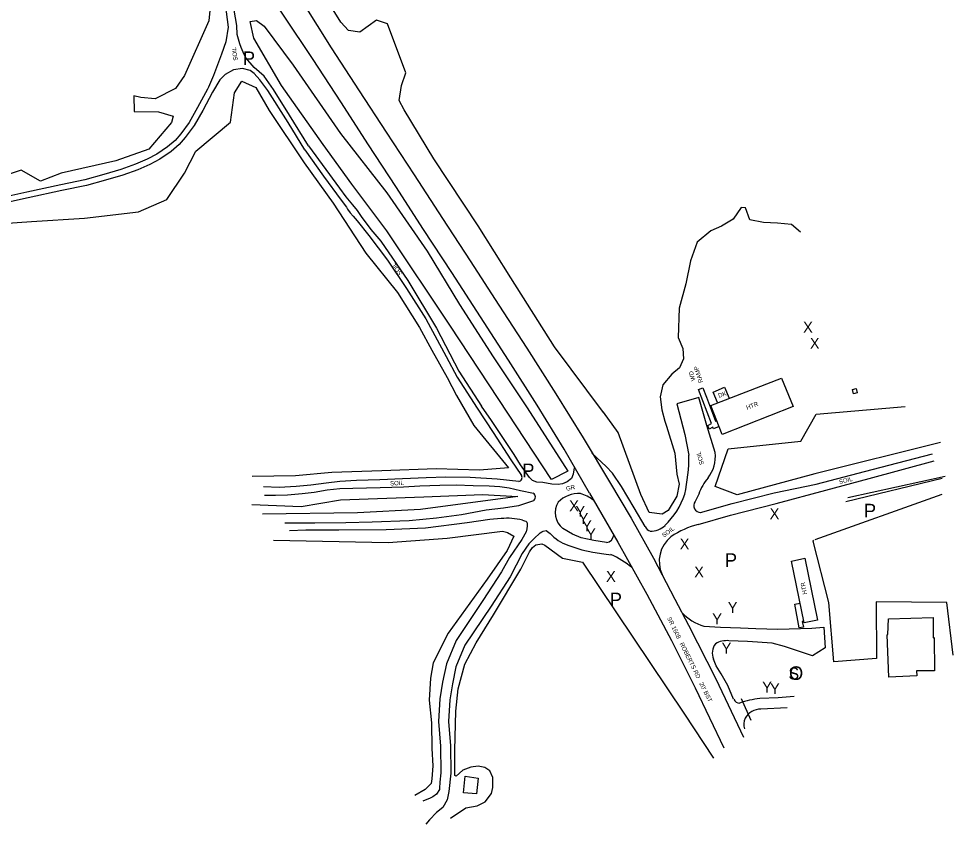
# Model space of a CAD drawing. Extents: x 2030130 to 2036320, y 723205 to 762423.
# Drawn here: x 2033690 to 2034549, y 732982 to 733722 of the extents above; entities that cross this region are included whole.
import ezdxf

# ---------------------------------------------------------------- set-up
doc = ezdxf.new("R2010")
doc.units = 0
for name, color, linetype in [('Draft_Station Cardinal Points', 7, 'Continuous'), ('Draft_Station Labels Major', 7, 'Continuous'), ('Draft_Station Tics Major', 7, 'Continuous'), ('Draft_Station Tics Minor', 7, 'Continuous'), ('Exist Terrain Model Ground Surface', 7, 'Continuous'), ('Old_Level_23', 7, 'Continuous'), ('Old_Level_28', 7, 'Continuous'), ('Prop Horizontal Alignment Ramp', 7, 'Continuous')]:
    doc.layers.add(name, color=color, linetype=linetype)

msp = doc.modelspace()

# ---------------------------------------------------------------- linework, layer by layer
at = {"layer": 'Draft_Station Labels Major'}
for points in [[(2033816.76, 733939.59), (2033844.08, 733898.19), (2033870.7, 733857.91), (2033897.82, 733817.12), (2033924.24, 733776.7), (2033951.46, 733736.85), (2033977.06, 733695.62), (2034003.01, 733656.12), (2034027.85, 733618.02), (2034053.46, 733578.96), (2034079.59, 733538.85), (2034105.07, 733499.79), (2034131.32, 733459.17), (2034157.01, 733419.63), (2034183.77, 733377.4), (2034208.78, 733337.17), (2034233.12, 733296.74)], [(2034214.62, 733286.13), (2034191.36, 733326.79), (2034166.47, 733367.19), (2034140.21, 733408.44), (2034114.52, 733448.22), (2034087.99, 733488.96), (2034062.14, 733528.76), (2034036.62, 733568.01), (2034011.49, 733606.61), (2033986.04, 733645.89), (2033960.58, 733684.87), (2033933.43, 733725.83), (2033907.56, 733765.32), (2033880.87, 733806.14), (2033853.87, 733846.93), (2033827.06, 733887.92), (2033800.46, 733927.9)], [(2033872.18, 733751.91), (2033878.14, 733738.45), (2033880.54, 733728.89), (2033882.42, 733714.57), (2033880.51, 733701.07), (2033876.55, 733689.95), (2033869.09, 733670.31), (2033864.55, 733659.36)], [(2033956.48, 733605.44), (2033938.88, 733633.83), (2033924.14, 733657.25), (2033915.56, 733669.51), (2033906.53, 733677.58), (2033898.7, 733686.37), (2033896.4, 733691.58), (2033894.45, 733695.98), (2033893.17, 733699.31), (2033890.84, 733707.77), (2033890.36, 733716.17), (2033888.02, 733730.23), (2033883.35, 733744.78), (2033878.11, 733756.35)], [(2033953.06, 733601.92), (2033937.54, 733627.03), (2033918.89, 733656.43), (2033911.71, 733666.22), (2033906.54, 733672.03), (2033902.69, 733674.86), (2033895.71, 733676.52), (2033887.3, 733675.4), (2033879.8, 733671.24), (2033874.81, 733666.13), (2033868.1, 733654.85), (2033859.1, 733638.17), (2033851.28, 733624.13), (2033843.07, 733613.19), (2033837.55, 733606.64), (2033830.1, 733600.27), (2033819.76, 733593.25), (2033810.49, 733588.5), (2033799.47, 733583.58), (2033785.58, 733578.7), (2033769.68, 733574.11), (2033752.18, 733569.2), (2033729.78, 733564.54), (2033698.66, 733557.66), (2033667.91, 733551.07)], [(2033864.55, 733659.36), (2033863.44, 733657.49), (2033854.4, 733640.74), (2033846.78, 733627.05), (2033838.88, 733616.52), (2033833.74, 733610.43), (2033826.84, 733604.53), (2033817.02, 733597.86), (2033808.17, 733593.33), (2033797.49, 733588.55), (2033783.95, 733583.8), (2033768.21, 733579.26), (2033750.91, 733574.4), (2033728.66, 733569.77), (2033697.52, 733562.89), (2033666.99, 733556.34), (2033640.15, 733552.65), (2033610.73, 733550.63)], [(2033956.48, 733605.44), (2033984.8, 733566.7), (2033990.59, 733558.79), (2033996.69, 733551.35), (2034000.94, 733546.13), (2034004.79, 733540.51), (2034013.63, 733528.69), (2034022.7, 733518.02), (2034047.62, 733481.65), (2034073.98, 733437.75), (2034094.5, 733398.36), (2034115.41, 733366.04)], [(2033953.06, 733601.92), (2033970.22, 733577.62), (2033986.31, 733555.7), (2033991.29, 733549.18), (2033992.18, 733547.2), (2033994.57, 733544), (2033997.35, 733540.77), (2034001.06, 733536.45), (2034011.67, 733523), (2034029.01, 733500.54), (2034046.28, 733474.29), (2034064.16, 733446.37), (2034082.94, 733411.8), (2034093.13, 733392.74), (2034111.29, 733364.32)], [(2034330.03, 733323.49), (2034322.43, 733348.39), (2034315.15, 733374.08), (2034294.72, 733368.21), (2034302.22, 733340.16), (2034305.97, 733321.17)], [(2034111.29, 733364.32), (2034126.04, 733341.85), (2034142.38, 733316.77), (2034151.97, 733302.33)], [(2034200.58, 733309.43), (2034199.52, 733303.76), (2034197.92, 733299.68), (2034194.19, 733296.55), (2034189.81, 733294.81), (2034185.66, 733294.05), (2034180.06, 733294.32), (2034171.85, 733295.85), (2034166.16, 733296.42), (2034162.28, 733297.91), (2034159.61, 733300.65), (2034151.3, 733312.11), (2034145.5, 733321.62), (2034124.43, 733352.94), (2034115.41, 733366.04)], [(2034265.62, 733255.45), (2034255.53, 733272.76), (2034243.93, 733292.19), (2034235.85, 733304.43), (2034230.04, 733310.6), (2034216.9, 733322.81)], [(2034316.76, 733268.55), (2034345.81, 733276.71), (2034384.46, 733286.64), (2034422.95, 733294.61), (2034474.37, 733307.8), (2034529.78, 733322.43)], [(2034314.58, 733257.51), (2034344.13, 733265.85), (2034386.05, 733276.67), (2034431.75, 733289.04), (2034471.6, 733299.82), (2034531.37, 733315.99)], [(2034149.55, 733296.99), (2034129.65, 733299.07), (2034105.02, 733300.71), (2034082.52, 733300.9), (2034064.51, 733300.37), (2034042.85, 733299.26), (2034021.88, 733298.32), (2034000.33, 733297.9), (2033985.26, 733296.78), (2033972.63, 733295.5), (2033958.61, 733293.56), (2033945.01, 733292.21), (2033929.25, 733291.51), (2033915.01, 733291.94)], [(2034233.12, 733296.74), (2034252.94, 733263.3), (2034273.44, 733226.3), (2034292.95, 733188.84), (2034305.49, 733164.67), (2034330.63, 733115.43), (2034356.14, 733061.96)], [(2034163.08, 733286.03), (2034151.15, 733288.26), (2034140.71, 733290.64), (2034132.19, 733291.88), (2034122.38, 733292.48), (2034107.84, 733292.92), (2034092.22, 733293.39), (2034077.08, 733293.36), (2034058.57, 733292.55), (2034043.61, 733291.83), (2034022.35, 733291.19), (2033996.97, 733290.49), (2033985.06, 733290.17), (2033973.62, 733288.84), (2033961.47, 733286.95), (2033950.41, 733285.52), (2033937.01, 733284.45), (2033925.89, 733284), (2033916.06, 733284.11)], [(2034163.16, 733279.08), (2034149.45, 733274.58), (2034135.72, 733272.44), (2034119.74, 733270.57), (2034097.1, 733266.34), (2034073.9, 733263.21), (2034048.95, 733260.83), (2034014.79, 733259.41), (2033990.7, 733259.06), (2033962.27, 733258.65), (2033934.64, 733258.51)], [(2034214.62, 733286.13), (2034240.53, 733241.21), (2034267.38, 733193.2), (2034289.88, 733150.64), (2034311.85, 733107.1), (2034338, 733052.14)], [(2034315, 733285.41), (2034311.77, 733278.44)], [(2034133.53, 733262.86), (2034123.08, 733261.9), (2034102.04, 733258.81), (2034063.85, 733254.07), (2034027.63, 733252.62), (2033984.36, 733252.26), (2033953.78, 733252.11), (2033939.02, 733251.58)], [(2034152.95, 733261.39), (2034154.89, 733260.84), (2034156.05, 733260.31), (2034156.91, 733259.5), (2034157.35, 733257.92), (2034157.39, 733256.05), (2034157.11, 733253.32), (2034156.34, 733250.5), (2034152.31, 733243.47), (2034141.03, 733227.15), (2034133.75, 733213.93)], [(2034230.18, 733240.73), (2034218.54, 733242.65), (2034207.02, 733245.17), (2034199.06, 733248.46), (2034190.01, 733253.68)], [(2034158.95, 733239.66), (2034164.41, 733245.18), (2034168.35, 733248.88), (2034169.35, 733249.64), (2034170.95, 733250.67), (2034172.04, 733251.22), (2034174.71, 733251.73), (2034178.34, 733249.21)], [(2034158.95, 733239.66), (2034152.86, 733230.82), (2034141.62, 733209.22), (2034124.14, 733182.32), (2034100.12, 733146.4), (2034091.87, 733126.47), (2034088.66, 733110.89), (2034086.24, 733096.07), (2034085.05, 733076.32), (2034086.92, 733053.92), (2034087.13, 733028.64), (2034085.25, 733011.84), (2034083.84, 733004.24), (2034079.7, 732997.12), (2034073.88, 732992.59), (2034067.6, 732985.73), (2034064.34, 732981.71)], [(2034194.82, 733238.38), (2034207.66, 733234.06), (2034217.63, 733231.89), (2034227.81, 733230.4), (2034234.43, 733229.62)], [(2034133.75, 733213.93), (2034133.7, 733213.83), (2034116.5, 733187.35), (2034092.01, 733150.74), (2034083.08, 733129.17), (2034079.65, 733112.55), (2034077.13, 733097.08), (2034075.88, 733076.21), (2034077.77, 733053.5), (2034077.97, 733029.11), (2034077, 733020.45)], [(2034319.75, 733163.75), (2034334.87, 733162.89), (2034353.53, 733162.33), (2034367.47, 733161.61), (2034387.61, 733161.09), (2034419, 733162.2), (2034429.84, 733163.05), (2034431.32, 733143.83), (2034419.5, 733136.62), (2034393.91, 733145.17), (2034382.4, 733148.27), (2034359.83, 733149.75), (2034342.75, 733150.56)], [(2034347.1, 733096.66), (2034341.78, 733109.31), (2034335.52, 733120.11), (2034331.03, 733127.33), (2034328.56, 733133.5)], [(2034402.77, 733099.15), (2034387.89, 733098.13), (2034371.15, 733097.36)], [(2034396.41, 733088.66), (2034372.1, 733087.53)], [(2034077.13, 733021.6), (2034076.7, 733013.77), (2034074.02, 733009.54), (2034070.61, 733007.1), (2034068.22, 733005.8), (2034061.48, 733003.07)]]:
    msp.add_lwpolyline(points, dxfattribs=at)
for centre, major_axis, ratio, start_param, end_param in [((2034150.39, 733320.37), (4.82, 161.99), 0.959957, 4.521895, 4.74591), ((2034299.4, 733319.59), (5.25, 30.54), 0.995887, 4.209414, 5.007966), ((2034149.22, 733300.36), (0.18, 3.38), 0.999144, 3.291126, 5.386237), ((2034366.97, 733265.7), (-38.33, -40.58), 0.994742, 4.796558, 5.104993), ((2034160.48, 733282.52), (-0.74, 4.3), 0.997986, 3.632272, 5.529454), ((2034201.64, 733268.17), (7.73, -16.94), 0.996971, 3.729479, 5.177531), ((2034204.69, 733259.4), (-25.25, 7.98), 0.997196, 4.957246, 5.812224), ((2034197.11, 733252.23), (-25.56, 23.73), 0.994601, 4.809034, 5.196654), ((2034234.99, 733307.87), (27.73, 65.77), 0.993405, 4.304944, 4.784898), ((2034316.64, 733274.69), (1.59, 5.93), 0.999801, 1.177557, 3.427058), ((2034140.26, 733208.56), (-54.92, 15.61), 0.951459, 4.751607, 5.095131), ((2034273.74, 733259.84), (-9.19, 0.9), 0.99896, 0.594356, 1.321947), ((2034271.03, 733269.97), (-12.2, -14.42), 0.989188, 0.669166, 1.473509), ((2034335.55, 733177.59), (-81.5, -14.15), 0.998914, 4.797058, 5.13178), ((2034207.51, 733276.37), (25.88, -31.25), 0.982401, 4.769537, 5.261256), ((2034229.14, 733248.45), (7.23, -2.91), 0.999526, 5.228569, 6.544658), ((2034308.05, 733223.36), (4.69, -29.07), 0.997482, 3.664018, 4.975671), ((2034202.68, 733157.4), (73.68, -30.95), 0.987199, 1.270268, 1.55658), ((2034333.45, 733208.23), (44.02, -15.54), 0.997069, 4.230993, 4.752922), ((2034341.33, 733127.77), (-4.72, 22.34), 0.997247, 6.012204, 6.576758), ((2034341.67, 733139.04), (4.72, -13.52), 0.993984, 3.720203, 4.776332), ((2034352.52, 733099.08), (5.67, -1.76), 0.99959, 3.86422, 5.026615), ((2034379.82, 733016.15), (24, 78.06), 0.999914, 0.404563, 0.638106), ((2034371.69, 733071.5), (15.85, 2.5), 0.999826, 1.382963, 2.475349), ((2034368.96, 733073.65), (-1.98, 12.47), 0.99999, 0.946566, 1.737886)]:
    msp.add_ellipse(centre, major_axis=major_axis, ratio=ratio, start_param=start_param, end_param=end_param, dxfattribs=at)
at = {"layer": 'Draft_Station Tics Major'}
for p, q in [((2034538.77, 733299.82), (2034450.32, 733278.28)), ((2034421.95, 733243.5), (2034538.7, 733285.34))]:
    msp.add_line(p, q, dxfattribs=at)
for points in [[(2033678.91, 733973.22), (2033735.96, 733904.64), (2033766.16, 733863.44), (2033805.15, 733816.65), (2033837.64, 733769.56), (2033854.94, 733752.02), (2033867.03, 733742.64), (2033864.71, 733720.45), (2033842.3, 733670.26), (2033834.19, 733658.4), (2033815.48, 733648.67), (2033802.21, 733649.97), (2033795.88, 733651.63), (2033796.21, 733637.09), (2033818.63, 733636.9), (2033832.06, 733632.75), (2033830.55, 733626.97), (2033809.73, 733602.6), (2033779.24, 733591.72), (2033728.97, 733580.44), (2033709.98, 733573.19), (2033692.26, 733583.23), (2033668.96, 733575.64)], [(2034045.79, 733672.8), (2034028.87, 733717.61), (2034019, 733721.11), (2034003.45, 733710.04), (2033993, 733711.54), (2033985.98, 733719.35), (2033979.15, 733730.47), (2033975.94, 733743.11), (2033981.71, 733755.28), (2033992, 733759.98), (2034004.37, 733762.28), (2034011.13, 733758.31), (2034025.04, 733751.04), (2034048.25, 733769.96), (2034049.7, 733788.36), (2034059.64, 733789.79), (2034081.59, 733786.3), (2034114.4, 733804.18), (2034142.7, 733823.58), (2034153.44, 733831.12), (2034156.35, 733838.98), (2034153, 733853.39)], [(2033969.96, 733606.63), (2033931.62, 733661.06), (2033906.09, 733704.5), (2033902.62, 733719.96), (2033908.44, 733720.66), (2033915.56, 733715.55), (2033942.11, 733679.64), (2033985.86, 733616.99)], [(2033622.79, 733530.53), (2033701.83, 733535.94), (2033750.45, 733538.88), (2033800.19, 733544.94), (2033826.22, 733556.33), (2033842.36, 733580.47), (2033852.68, 733600.51), (2033884.81, 733627.16), (2033888.36, 733654.21), (2033895.16, 733665.05), (2033907.86, 733659.1), (2033920.3, 733637.98), (2033952.27, 733589.84)], [(2034227.56, 733360.48), (2034182.55, 733420.78), (2034142.33, 733484.09), (2034112.36, 733532.03), (2034071.39, 733593.72), (2034044.4, 733638.72), (2034039.7, 733647.36), (2034041.81, 733660.87), (2034045.79, 733672.8)], [(2033985.86, 733616.99), (2034028.28, 733562.23), (2034065.5, 733508.75), (2034095.24, 733459.76), (2034126.17, 733411.49), (2034157.36, 733364.67)], [(2034139.68, 733359.67), (2034086.94, 733439.81), (2034028.2, 733527.28), (2033996.27, 733570.15), (2033969.96, 733606.63)], [(2033952.27, 733589.84), (2033979.1, 733552.71), (2034009.16, 733506.81), (2034038.26, 733470.66), (2034058.3, 733438.57), (2034069.78, 733417.71), (2034083.89, 733392.56), (2034092.25, 733376.1), (2034108.2, 733348.35)], [(2034408.55, 733526.23), (2034400.39, 733533.07), (2034387.33, 733534.29), (2034374.44, 733535.01), (2034362.02, 733537.56), (2034358.01, 733548.6), (2034354.14, 733548.86), (2034346.61, 733538.19), (2034335.86, 733531.74), (2034326.16, 733527.29), (2034313.49, 733516.83), (2034307.46, 733499.89), (2034303.09, 733478.71), (2034297.12, 733456.24), (2034296.01, 733429.29), (2034300.36, 733419.3), (2034300.94, 733409.76), (2034297.2, 733401.47), (2034290.17, 733395.74), (2034282.09, 733385.78), (2034279.6, 733374.91), (2034280.95, 733362.71), (2034283.92, 733352.3), (2034285.48, 733347.77)], [(2034157.36, 733364.67), (2034194.59, 733306.51), (2034179.65, 733298.74), (2034139.68, 733359.67)], [(2034537.28, 733332.91), (2034421.57, 733304.1), (2034350.43, 733284.51), (2034330.1, 733292.38), (2034342.13, 733327.09), (2034408.97, 733334.07), (2034422.85, 733358.73), (2034504.86, 733365.73)], [(2034285.48, 733347.77), (2034293.08, 733322.96), (2034294.95, 733303.63), (2034297.13, 733294.42), (2034294.92, 733283.38), (2034286.76, 733270.35), (2034281.34, 733266.88), (2034269.39, 733268.33), (2034261.74, 733285.08), (2034240.96, 733341.95), (2034227.43, 733360.65)], [(2034108.18, 733348.38), (2034140.31, 733309.58), (2034113.4, 733307.46), (2034073.65, 733308.47), (2034023.82, 733306.66), (2033977.93, 733305.31), (2033944.52, 733302.22), (2033904.52, 733301.47)], [(2034452.14, 733282.22), (2034541.63, 733301.81)], [(2033904.13, 733275.82), (2033949.54, 733274.04), (2033985.78, 733279.99), (2034062.29, 733282.76), (2034116.24, 733284.84), (2034148.71, 733283.07), (2034059.39, 733271.29), (2034001.29, 733267.96), (2033914.05, 733266.89)], [(2033924.3, 733243.06), (2034029.66, 733240.84), (2034083.86, 733244.67), (2034134.62, 733251.36), (2034139.52, 733250.07)], [(2034139.14, 733250.17), (2034145.11, 733246.66), (2034138.83, 733233.52), (2034120.59, 733207.23), (2034084.78, 733157.37), (2034071.02, 733130.16), (2034068.43, 733116.13), (2034067.23, 733095.79), (2034069.34, 733074.95), (2034069.8, 733051.42), (2034070.68, 733035.52), (2034069.73, 733023.6), (2034069.01, 733019.12), (2034063.55, 733013.6), (2034053.98, 733008.21)], [(2034086.85, 732987.41), (2034101.06, 732996.98), (2034111.3, 732998.62), (2034118.86, 733002.51), (2034124.58, 733009.98), (2034125.72, 733015.43), (2034125.62, 733024.84), (2034122.87, 733031), (2034118.45, 733033.87), (2034112.41, 733035.04), (2034105.53, 733034.27), (2034098.19, 733031.36), (2034092.15, 733026.05), (2034090.79, 733026.49), (2034090.91, 733049.8), (2034091.61, 733085.64), (2034093.81, 733106.35), (2034100.18, 733128.88), (2034110.43, 733148.45), (2034126.5, 733174.42), (2034151.48, 733216.18), (2034159.61, 733232.2), (2034162.28, 733236.23), (2034165.3, 733238.68), (2034170.82, 733239.69), (2034173.44, 733238.41)], [(2034173.44, 733238.41), (2034189.91, 733226.55), (2034208.22, 733222.86), (2034301.38, 733084.03), (2034328.53, 733042.44)], [(2034548.96, 733137.18), (2034542.99, 733185.77), (2034477.95, 733186.18), (2034478.52, 733134.23), (2034439.04, 733131.12), (2034434.43, 733185.74), (2034420.27, 733242.02), (2034420.87, 733242.82)]]:
    msp.add_lwpolyline(points, dxfattribs=at)
at = {"layer": 'Draft_Station Tics Minor'}
msp.add_lwpolyline([(2034354.11, 733097.49), (2034362.95, 733077.33)], dxfattribs=at)
at = {"layer": 'Exist Terrain Model Ground Surface'}
for points in [[(2034325.97, 733366.69), (2034391, 733391.98), (2034401.67, 733365.81), (2034336.63, 733340.13)], [(2034456.31, 733381.53), (2034459.65, 733382.46), (2034460.45, 733378.45), (2034457.21, 733377.61)], [(2034411.85, 733166.89), (2034400.31, 733223.78), (2034412.39, 733226.45), (2034424.02, 733169.37)], [(2034489.67, 733116.94), (2034488.04, 733155.95), (2034488.73, 733156.12), (2034489.27, 733170.56), (2034530.6, 733171.86), (2034530.43, 733153.28), (2034531.52, 733153.45), (2034531.67, 733122.87), (2034515.15, 733122.78), (2034515.4, 733118.15)], [(2034100.49, 733026.01), (2034112.39, 733024.27), (2034110.77, 733009.63), (2034098.85, 733010.77)]]:
    msp.add_lwpolyline(points, close=True, dxfattribs=at)
for points in [[(2034333.67, 733347.5), (2034328.5, 733345.39), (2034327.95, 733346.79), (2034324.65, 733345.12), (2034323.27, 733348.3), (2034326.67, 733350.17), (2034314.85, 733381.5), (2034318.63, 733383.05), (2034322.01, 733374.49), (2034330.28, 733352.42), (2034331.5, 733352.9)], [(2034332.2, 733369.43), (2034328.22, 733378.93), (2034338.7, 733383.55), (2034342.88, 733373.38)], [(2034411.57, 733168.29), (2034410.19, 733168.13), (2034411.3, 733162.89), (2034407.45, 733162.31), (2034403.21, 733184.27), (2034408.14, 733185.19)]]:
    msp.add_lwpolyline(points, dxfattribs=at)

# ---------------------------------------------------------------- texts
at = {"layer": 'Draft_Station Cardinal Points'}
for s, height, p in [('S', 11, (2034397.46, 733114.87)), ('O', 12.5, (2034398, 733114.47))]:
    msp.add_text(s, height=height, dxfattribs=at).set_placement(p)
at = {"layer": 'Draft_Station Tics Major'}
for s, p in [('X', (2034410.93, 733433.73)), ('X', (2034417.12, 733418.91)), ('X', (2034195.9, 733269.46)), ('Y', (2034201.69, 733264.45)), ('X', (2034380.18, 733262.24)), ('Y', (2034204.63, 733257.89)), ('Y', (2034207.75, 733251.13)), ('Y', (2034211.45, 733243.77)), ('X', (2034297.51, 733234.42)), ('X', (2034310.84, 733208.74)), ('X', (2034229.85, 733204.61)), ('Y', (2034341.66, 733176.12)), ('Y', (2034327.43, 733165.58)), ('Y', (2034336.01, 733138.67)), ('Y', (2034373.33, 733102.85)), ('Y', (2034380.54, 733101.45))]:
    msp.add_text(s, height=10, dxfattribs=at).set_placement(p)
at = {"layer": 'Old_Level_23'}
for s, rotation, p in [('SOIL', 98.08157, (2033891.4, 733684.2)), ('SOIL', 124.20596, (2034042.69, 733488.14)), ('SOIL', 105.82425, (2034319.81, 733312.89)), ('SOIL', 2.46424, (2034031.44, 733293.2)), ('SOIL', 13.69781, (2034444.46, 733294.55)), ('GR', 12.31489, (2034193.51, 733288.26)), ('SOIL', 37.25075, (2034283.1, 733245.2)), ("SR 1608   ROBERTS RD   20' BST", 296.24998, (2034285.81, 733171.14))]:
    msp.add_text(s, height=4, rotation=rotation, dxfattribs=at).set_placement(p)
at = {"layer": 'Old_Level_28'}
for s, rotation, p in [('RAMP', 107.55142, (2034319.04, 733388.25)), ('WD', 107.55142, (2034312.16, 733390.11)), ('DK', 18.93416, (2034333.65, 733373.79)), ('HTR', 20.05551, (2034359.43, 733362.84)), ('HTR', 101.63331, (2034414.71, 733193.51))]:
    msp.add_text(s, height=4, rotation=rotation, dxfattribs=at).set_placement(p)
at = {"layer": 'Prop Horizontal Alignment Ramp'}
for p in [(2033896.11, 733679.8), (2034152.84, 733300.85), (2034466.85, 733263.88), (2034339.03, 733218.41), (2034233.27, 733182.18)]:
    msp.add_text('P', height=12.5, dxfattribs=at).set_placement(p)

doc.saveas('drawing.dxf')
